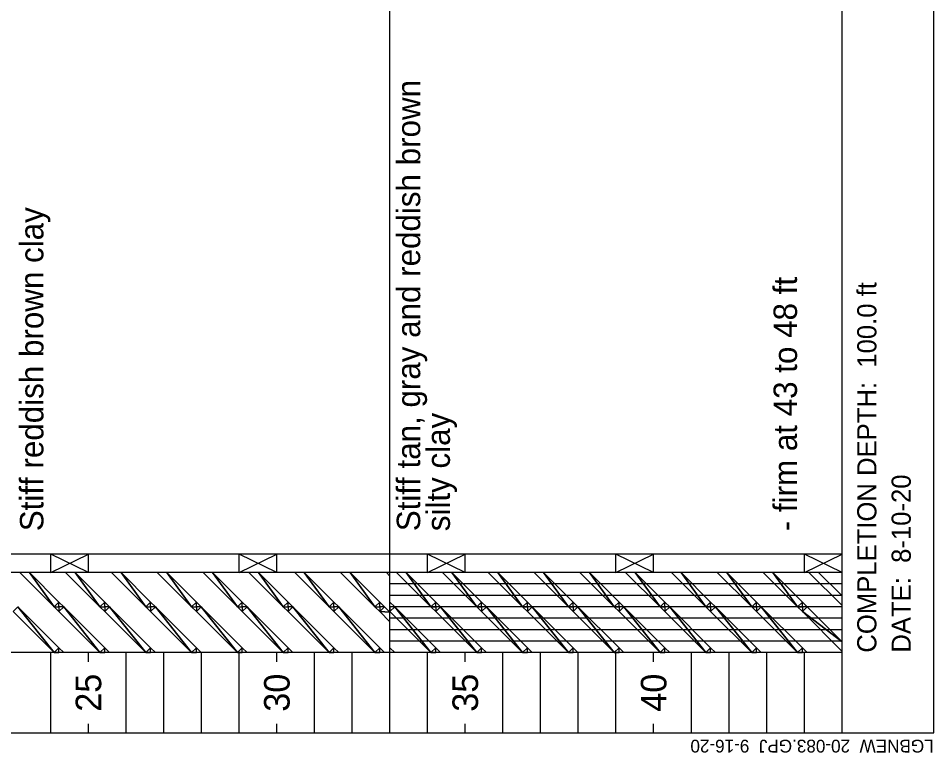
# Model space of a CAD drawing. Extents: x 1313964 to 1316843, y 2087046 to 2096619.
# Drawn here: x 1314012.51 to 1314036.8, y 2089818.18 to 2089837.67 of the extents above; entities that cross this region are included whole.
import ezdxf

# ---------------------------------------------------------------- set-up
doc = ezdxf.new("R2010")
doc.units = 0
doc.layers.add('B-Sub-Contour', color=7, linetype='Continuous')

msp = doc.modelspace()

# ---------------------------------------------------------------- linework, layer by layer
at = {"layer": 'B-Sub-Contour'}
for points in [[(1314036.804, 2089818.705), (1314036.804, 2089861.576), (1313975.385, 2089861.576), (1313975.385, 2089818.705), (1314036.804, 2089818.705)], [(1314034.372, 2089818.705), (1314034.372, 2089861.576)], [(1314022.372, 2089823.448), (1314022.372, 2089839.319)], [(1314034.372, 2089823.448), (1313989.372, 2089823.448)], [(1314013.372, 2089822.961), (1314014.372, 2089823.448)], [(1314014.372, 2089822.961), (1314013.372, 2089823.448)], [(1314013.372, 2089822.961), (1314013.372, 2089823.448)], [(1314014.372, 2089822.961), (1314014.372, 2089823.448)], [(1314018.372, 2089822.961), (1314019.372, 2089823.448)], [(1314019.372, 2089822.961), (1314018.372, 2089823.448)], [(1314018.372, 2089822.961), (1314018.372, 2089823.448)], [(1314019.372, 2089822.961), (1314019.372, 2089823.448)], [(1314022.372, 2089822.961), (1314022.372, 2089823.448)], [(1314023.372, 2089822.961), (1314024.372, 2089823.448)], [(1314024.372, 2089822.961), (1314023.372, 2089823.448)], [(1314023.372, 2089822.961), (1314023.372, 2089823.448)], [(1314024.372, 2089822.961), (1314024.372, 2089823.448)], [(1314028.372, 2089822.961), (1314029.372, 2089823.448)], [(1314029.372, 2089822.961), (1314028.372, 2089823.448)], [(1314028.372, 2089822.961), (1314028.372, 2089823.448)], [(1314029.372, 2089822.961), (1314029.372, 2089823.448)], [(1314033.372, 2089822.961), (1314034.372, 2089823.448)], [(1314034.372, 2089822.961), (1314033.372, 2089823.448)], [(1314033.372, 2089822.961), (1314033.372, 2089823.448)], [(1314034.372, 2089822.961), (1314034.372, 2089823.448)], [(1314034.372, 2089822.961), (1313982.683, 2089822.961)], [(1314022.372, 2089820.833), (1314022.372, 2089822.961)], [(1314034.372, 2089822.657), (1314022.372, 2089822.657)], [(1314034.372, 2089822.353), (1314022.372, 2089822.353)], [(1314034.372, 2089822.049), (1314022.372, 2089822.049)], [(1314034.372, 2089821.745), (1314022.372, 2089821.745)], [(1314034.372, 2089821.441), (1314022.372, 2089821.441)], [(1314034.372, 2089821.137), (1314022.372, 2089821.137)], [(1314034.372, 2089820.833), (1313982.683, 2089820.833)], [(1314013.372, 2089818.705), (1314013.372, 2089820.833)], [(1314013.372, 2089818.705), (1314013.372, 2089820.833)], [(1314014.372, 2089820.59), (1314014.372, 2089820.833)], [(1314015.372, 2089818.705), (1314015.372, 2089820.833)], [(1314015.372, 2089818.705), (1314015.372, 2089820.833)], [(1314016.372, 2089818.705), (1314016.372, 2089820.833)], [(1314017.372, 2089818.705), (1314017.372, 2089820.833)], [(1314017.372, 2089818.705), (1314017.372, 2089820.833)], [(1314018.372, 2089818.705), (1314018.372, 2089820.833)], [(1314019.372, 2089820.59), (1314019.372, 2089820.833)], [(1314019.372, 2089820.59), (1314019.372, 2089820.833)], [(1314020.372, 2089818.705), (1314020.372, 2089820.833)], [(1314021.372, 2089818.705), (1314021.372, 2089820.833)], [(1314021.372, 2089818.705), (1314021.372, 2089820.833)], [(1314022.372, 2089818.705), (1314022.372, 2089820.833)], [(1314023.372, 2089818.705), (1314023.372, 2089820.833)], [(1314023.372, 2089818.705), (1314023.372, 2089820.833)], [(1314024.372, 2089820.59), (1314024.372, 2089820.833)], [(1314025.372, 2089818.705), (1314025.372, 2089820.833)], [(1314025.372, 2089818.705), (1314025.372, 2089820.833)], [(1314026.372, 2089818.705), (1314026.372, 2089820.833)], [(1314027.372, 2089818.705), (1314027.372, 2089820.833)], [(1314027.372, 2089818.705), (1314027.372, 2089820.833)], [(1314028.372, 2089818.705), (1314028.372, 2089820.833)], [(1314029.372, 2089820.59), (1314029.372, 2089820.833)], [(1314029.372, 2089820.59), (1314029.372, 2089820.833)], [(1314030.372, 2089818.705), (1314030.372, 2089820.833)], [(1314031.372, 2089818.705), (1314031.372, 2089820.833)], [(1314031.372, 2089818.705), (1314031.372, 2089820.833)], [(1314032.372, 2089818.705), (1314032.372, 2089820.833)], [(1314033.372, 2089818.705), (1314033.372, 2089820.833)], [(1314033.372, 2089818.705), (1314033.372, 2089820.833)], [(1314034.372, 2089820.59), (1314034.372, 2089820.833)], [(1314014.372, 2089818.705), (1314014.372, 2089818.948)], [(1314019.372, 2089818.705), (1314019.372, 2089818.948)], [(1314019.372, 2089818.705), (1314019.372, 2089818.948)], [(1314024.372, 2089818.705), (1314024.372, 2089818.948)], [(1314029.372, 2089818.705), (1314029.372, 2089818.948)], [(1314029.372, 2089818.705), (1314029.372, 2089818.948)], [(1314034.372, 2089818.705), (1314034.372, 2089818.948)]]:
    msp.add_lwpolyline(points, dxfattribs=at)
for points in [[(1314013.46, 2089822.049), (1314012.803, 2089822.961), (1314012.547, 2089822.961), (1314013.46, 2089822.049)], [(1314013.46, 2089822.049), (1314013.588, 2089822.177), (1314012.803, 2089822.961), (1314013.46, 2089822.049)], [(1314014.676, 2089822.049), (1314014.02, 2089822.961), (1314013.764, 2089822.961), (1314014.676, 2089822.049)], [(1314014.676, 2089822.049), (1314014.804, 2089822.177), (1314014.02, 2089822.961), (1314014.676, 2089822.049)], [(1314015.893, 2089822.049), (1314015.236, 2089822.961), (1314014.98, 2089822.961), (1314015.893, 2089822.049)], [(1314015.893, 2089822.049), (1314016.02, 2089822.177), (1314015.236, 2089822.961), (1314015.893, 2089822.049)], [(1314017.109, 2089822.049), (1314016.452, 2089822.961), (1314016.197, 2089822.961), (1314017.109, 2089822.049)], [(1314017.109, 2089822.049), (1314017.237, 2089822.177), (1314016.452, 2089822.961), (1314017.109, 2089822.049)], [(1314018.325, 2089822.049), (1314017.668, 2089822.961), (1314017.413, 2089822.961), (1314018.325, 2089822.049)], [(1314018.325, 2089822.049), (1314018.453, 2089822.177), (1314017.668, 2089822.961), (1314018.325, 2089822.049)], [(1314019.541, 2089822.049), (1314018.884, 2089822.961), (1314018.629, 2089822.961), (1314019.541, 2089822.049)], [(1314019.541, 2089822.049), (1314019.669, 2089822.177), (1314018.884, 2089822.961), (1314019.541, 2089822.049)], [(1314020.757, 2089822.049), (1314020.101, 2089822.961), (1314019.845, 2089822.961), (1314020.757, 2089822.049)], [(1314020.757, 2089822.049), (1314020.885, 2089822.177), (1314020.101, 2089822.961), (1314020.757, 2089822.049)], [(1314021.974, 2089822.049), (1314021.317, 2089822.961), (1314021.062, 2089822.961), (1314021.974, 2089822.049)], [(1314021.974, 2089822.049), (1314022.101, 2089822.177), (1314021.317, 2089822.961), (1314021.974, 2089822.049)], [(1314022.372, 2089822.867), (1314022.372, 2089822.961), (1314022.278, 2089822.961), (1314022.372, 2089822.867)], [(1314023.46, 2089822.049), (1314022.803, 2089822.961), (1314022.547, 2089822.961), (1314023.46, 2089822.049)], [(1314023.46, 2089822.049), (1314023.588, 2089822.177), (1314022.803, 2089822.961), (1314023.46, 2089822.049)], [(1314024.676, 2089822.049), (1314024.02, 2089822.961), (1314023.764, 2089822.961), (1314024.676, 2089822.049)], [(1314024.676, 2089822.049), (1314024.804, 2089822.177), (1314024.02, 2089822.961), (1314024.676, 2089822.049)], [(1314025.893, 2089822.049), (1314025.236, 2089822.961), (1314024.98, 2089822.961), (1314025.893, 2089822.049)], [(1314025.893, 2089822.049), (1314026.02, 2089822.177), (1314025.236, 2089822.961), (1314025.893, 2089822.049)], [(1314027.109, 2089822.049), (1314026.452, 2089822.961), (1314026.197, 2089822.961), (1314027.109, 2089822.049)], [(1314027.109, 2089822.049), (1314027.236, 2089822.177), (1314026.452, 2089822.961), (1314027.109, 2089822.049)], [(1314028.325, 2089822.049), (1314027.668, 2089822.961), (1314027.413, 2089822.961), (1314028.325, 2089822.049)], [(1314028.325, 2089822.049), (1314028.453, 2089822.177), (1314027.668, 2089822.961), (1314028.325, 2089822.049)], [(1314029.541, 2089822.049), (1314028.884, 2089822.961), (1314028.629, 2089822.961), (1314029.541, 2089822.049)], [(1314029.541, 2089822.049), (1314029.669, 2089822.177), (1314028.884, 2089822.961), (1314029.541, 2089822.049)], [(1314030.757, 2089822.049), (1314030.101, 2089822.961), (1314029.845, 2089822.961), (1314030.757, 2089822.049)], [(1314030.757, 2089822.049), (1314030.885, 2089822.177), (1314030.101, 2089822.961), (1314030.757, 2089822.049)], [(1314031.974, 2089822.049), (1314031.317, 2089822.961), (1314031.061, 2089822.961), (1314031.974, 2089822.049)], [(1314031.974, 2089822.049), (1314032.101, 2089822.177), (1314031.317, 2089822.961), (1314031.974, 2089822.049)], [(1314033.19, 2089822.049), (1314032.533, 2089822.961), (1314032.278, 2089822.961), (1314033.19, 2089822.049)], [(1314033.19, 2089822.049), (1314033.318, 2089822.177), (1314032.533, 2089822.961), (1314033.19, 2089822.049)], [(1314033.749, 2089822.961), (1314033.494, 2089822.961), (1314034.372, 2089822.084), (1314034.372, 2089822.339)], [(1314013.46, 2089822.049), (1314013.588, 2089822.049), (1314013.588, 2089822.177), (1314013.46, 2089822.049)], [(1314013.716, 2089822.049), (1314013.588, 2089822.049), (1314013.588, 2089822.177), (1314013.716, 2089822.049)], [(1314014.676, 2089822.049), (1314014.804, 2089822.049), (1314014.804, 2089822.177), (1314014.676, 2089822.049)], [(1314014.932, 2089822.049), (1314014.804, 2089822.049), (1314014.804, 2089822.177), (1314014.932, 2089822.049)], [(1314015.893, 2089822.049), (1314016.02, 2089822.049), (1314016.02, 2089822.177), (1314015.893, 2089822.049)], [(1314016.148, 2089822.049), (1314016.02, 2089822.049), (1314016.02, 2089822.177), (1314016.148, 2089822.049)], [(1314017.109, 2089822.049), (1314017.237, 2089822.049), (1314017.237, 2089822.177), (1314017.109, 2089822.049)], [(1314017.364, 2089822.049), (1314017.237, 2089822.049), (1314017.237, 2089822.177), (1314017.364, 2089822.049)], [(1314018.325, 2089822.049), (1314018.453, 2089822.049), (1314018.453, 2089822.177), (1314018.325, 2089822.049)], [(1314018.58, 2089822.049), (1314018.453, 2089822.049), (1314018.453, 2089822.177), (1314018.58, 2089822.049)], [(1314019.541, 2089822.049), (1314019.669, 2089822.049), (1314019.669, 2089822.177), (1314019.541, 2089822.049)], [(1314019.797, 2089822.049), (1314019.669, 2089822.049), (1314019.669, 2089822.177), (1314019.797, 2089822.049)], [(1314020.757, 2089822.049), (1314020.885, 2089822.049), (1314020.885, 2089822.177), (1314020.757, 2089822.049)], [(1314021.013, 2089822.049), (1314020.885, 2089822.049), (1314020.885, 2089822.177), (1314021.013, 2089822.049)], [(1314021.974, 2089822.049), (1314022.101, 2089822.049), (1314022.101, 2089822.177), (1314021.974, 2089822.049)], [(1314022.229, 2089822.049), (1314022.101, 2089822.049), (1314022.101, 2089822.177), (1314022.229, 2089822.049)], [(1314022.499, 2089822.049), (1314022.372, 2089822.049), (1314022.372, 2089822.177), (1314022.499, 2089822.049)], [(1314023.46, 2089822.049), (1314023.588, 2089822.049), (1314023.588, 2089822.177), (1314023.46, 2089822.049)], [(1314023.716, 2089822.049), (1314023.588, 2089822.049), (1314023.588, 2089822.177), (1314023.716, 2089822.049)], [(1314024.676, 2089822.049), (1314024.804, 2089822.049), (1314024.804, 2089822.177), (1314024.676, 2089822.049)], [(1314024.932, 2089822.049), (1314024.804, 2089822.049), (1314024.804, 2089822.177), (1314024.932, 2089822.049)], [(1314025.893, 2089822.049), (1314026.02, 2089822.049), (1314026.02, 2089822.177), (1314025.893, 2089822.049)], [(1314026.148, 2089822.049), (1314026.02, 2089822.049), (1314026.02, 2089822.177), (1314026.148, 2089822.049)], [(1314027.109, 2089822.049), (1314027.236, 2089822.049), (1314027.236, 2089822.177), (1314027.109, 2089822.049)], [(1314027.364, 2089822.049), (1314027.236, 2089822.049), (1314027.236, 2089822.177), (1314027.364, 2089822.049)], [(1314028.325, 2089822.049), (1314028.453, 2089822.049), (1314028.453, 2089822.177), (1314028.325, 2089822.049)], [(1314028.58, 2089822.049), (1314028.453, 2089822.049), (1314028.453, 2089822.177), (1314028.58, 2089822.049)], [(1314029.541, 2089822.049), (1314029.669, 2089822.049), (1314029.669, 2089822.177), (1314029.541, 2089822.049)], [(1314029.797, 2089822.049), (1314029.669, 2089822.049), (1314029.669, 2089822.177), (1314029.797, 2089822.049)], [(1314030.757, 2089822.049), (1314030.885, 2089822.049), (1314030.885, 2089822.177), (1314030.757, 2089822.049)], [(1314031.013, 2089822.049), (1314030.885, 2089822.049), (1314030.885, 2089822.177), (1314031.013, 2089822.049)], [(1314031.974, 2089822.049), (1314032.101, 2089822.049), (1314032.101, 2089822.177), (1314031.974, 2089822.049)], [(1314032.229, 2089822.049), (1314032.101, 2089822.049), (1314032.101, 2089822.177), (1314032.229, 2089822.049)], [(1314033.19, 2089822.049), (1314033.318, 2089822.049), (1314033.318, 2089822.177), (1314033.19, 2089822.049)], [(1314033.445, 2089822.049), (1314033.318, 2089822.049), (1314033.318, 2089822.177), (1314033.445, 2089822.049)], [(1314013.46, 2089820.833), (1314012.499, 2089822.049), (1314012.372, 2089821.922), (1314013.46, 2089820.833)], [(1314013.46, 2089820.833), (1314013.588, 2089820.961), (1314012.499, 2089822.049), (1314013.46, 2089820.833)], [(1314013.588, 2089822.049), (1314013.588, 2089821.922), (1314013.46, 2089822.049), (1314013.588, 2089822.049)], [(1314013.716, 2089822.049), (1314013.588, 2089822.049), (1314013.588, 2089821.922), (1314013.716, 2089822.049)], [(1314014.676, 2089820.833), (1314013.716, 2089822.049), (1314013.588, 2089821.922), (1314014.676, 2089820.833)], [(1314014.676, 2089820.833), (1314014.804, 2089820.961), (1314013.716, 2089822.049), (1314014.676, 2089820.833)], [(1314014.804, 2089822.049), (1314014.804, 2089821.922), (1314014.676, 2089822.049), (1314014.804, 2089822.049)], [(1314014.932, 2089822.049), (1314014.804, 2089822.049), (1314014.804, 2089821.922), (1314014.932, 2089822.049)], [(1314015.893, 2089820.833), (1314014.932, 2089822.049), (1314014.804, 2089821.922), (1314015.893, 2089820.833)], [(1314015.893, 2089820.833), (1314016.02, 2089820.961), (1314014.932, 2089822.049), (1314015.893, 2089820.833)], [(1314016.02, 2089822.049), (1314016.02, 2089821.922), (1314015.893, 2089822.049), (1314016.02, 2089822.049)], [(1314016.148, 2089822.049), (1314016.02, 2089822.049), (1314016.02, 2089821.922), (1314016.148, 2089822.049)], [(1314017.109, 2089820.833), (1314016.148, 2089822.049), (1314016.02, 2089821.922), (1314017.109, 2089820.833)], [(1314017.109, 2089820.833), (1314017.237, 2089820.961), (1314016.148, 2089822.049), (1314017.109, 2089820.833)], [(1314017.237, 2089822.049), (1314017.237, 2089821.922), (1314017.109, 2089822.049), (1314017.237, 2089822.049)], [(1314017.364, 2089822.049), (1314017.237, 2089822.049), (1314017.237, 2089821.922), (1314017.364, 2089822.049)], [(1314018.325, 2089820.833), (1314017.364, 2089822.049), (1314017.237, 2089821.922), (1314018.325, 2089820.833)], [(1314018.325, 2089820.833), (1314018.453, 2089820.961), (1314017.364, 2089822.049), (1314018.325, 2089820.833)], [(1314018.453, 2089822.049), (1314018.453, 2089821.922), (1314018.325, 2089822.049), (1314018.453, 2089822.049)], [(1314018.58, 2089822.049), (1314018.453, 2089822.049), (1314018.453, 2089821.922), (1314018.58, 2089822.049)], [(1314019.541, 2089820.833), (1314018.58, 2089822.049), (1314018.453, 2089821.922), (1314019.541, 2089820.833)], [(1314019.541, 2089820.833), (1314019.669, 2089820.961), (1314018.58, 2089822.049), (1314019.541, 2089820.833)], [(1314019.669, 2089822.049), (1314019.669, 2089821.922), (1314019.541, 2089822.049), (1314019.669, 2089822.049)], [(1314019.797, 2089822.049), (1314019.669, 2089822.049), (1314019.669, 2089821.922), (1314019.797, 2089822.049)], [(1314020.757, 2089820.833), (1314019.797, 2089822.049), (1314019.669, 2089821.922), (1314020.757, 2089820.833)], [(1314020.757, 2089820.833), (1314020.885, 2089820.961), (1314019.797, 2089822.049), (1314020.757, 2089820.833)], [(1314020.885, 2089822.049), (1314020.885, 2089821.922), (1314020.757, 2089822.049), (1314020.885, 2089822.049)], [(1314021.013, 2089822.049), (1314020.885, 2089822.049), (1314020.885, 2089821.922), (1314021.013, 2089822.049)], [(1314021.974, 2089820.833), (1314021.013, 2089822.049), (1314020.885, 2089821.922), (1314021.974, 2089820.833)], [(1314021.974, 2089820.833), (1314022.101, 2089820.961), (1314021.013, 2089822.049), (1314021.974, 2089820.833)], [(1314022.101, 2089822.049), (1314022.101, 2089821.922), (1314021.974, 2089822.049), (1314022.101, 2089822.049)], [(1314022.229, 2089822.049), (1314022.101, 2089822.049), (1314022.101, 2089821.922), (1314022.229, 2089822.049)], [(1314022.101, 2089821.922), (1314022.372, 2089821.907), (1314022.229, 2089822.049), (1314022.101, 2089821.922)], [(1314022.499, 2089822.049), (1314022.372, 2089822.049), (1314022.372, 2089821.922), (1314022.499, 2089822.049)], [(1314023.46, 2089820.833), (1314022.499, 2089822.049), (1314022.372, 2089821.922), (1314023.46, 2089820.833)], [(1314023.46, 2089820.833), (1314023.588, 2089820.961), (1314022.499, 2089822.049), (1314023.46, 2089820.833)], [(1314023.588, 2089822.049), (1314023.588, 2089821.922), (1314023.46, 2089822.049), (1314023.588, 2089822.049)], [(1314023.716, 2089822.049), (1314023.588, 2089822.049), (1314023.588, 2089821.922), (1314023.716, 2089822.049)], [(1314024.676, 2089820.833), (1314023.716, 2089822.049), (1314023.588, 2089821.922), (1314024.676, 2089820.833)], [(1314024.676, 2089820.833), (1314024.804, 2089820.961), (1314023.716, 2089822.049), (1314024.676, 2089820.833)], [(1314024.804, 2089822.049), (1314024.804, 2089821.922), (1314024.676, 2089822.049), (1314024.804, 2089822.049)], [(1314024.932, 2089822.049), (1314024.804, 2089822.049), (1314024.804, 2089821.922), (1314024.932, 2089822.049)], [(1314025.893, 2089820.833), (1314024.932, 2089822.049), (1314024.804, 2089821.922), (1314025.893, 2089820.833)], [(1314025.893, 2089820.833), (1314026.02, 2089820.961), (1314024.932, 2089822.049), (1314025.893, 2089820.833)], [(1314026.02, 2089822.049), (1314026.02, 2089821.922), (1314025.893, 2089822.049), (1314026.02, 2089822.049)], [(1314026.148, 2089822.049), (1314026.02, 2089822.049), (1314026.02, 2089821.922), (1314026.148, 2089822.049)], [(1314027.109, 2089820.833), (1314026.148, 2089822.049), (1314026.02, 2089821.922), (1314027.109, 2089820.833)], [(1314027.109, 2089820.833), (1314027.236, 2089820.961), (1314026.148, 2089822.049), (1314027.109, 2089820.833)], [(1314027.236, 2089822.049), (1314027.236, 2089821.922), (1314027.109, 2089822.049), (1314027.236, 2089822.049)], [(1314027.364, 2089822.049), (1314027.236, 2089822.049), (1314027.236, 2089821.922), (1314027.364, 2089822.049)], [(1314028.325, 2089820.833), (1314027.364, 2089822.049), (1314027.236, 2089821.922), (1314028.325, 2089820.833)], [(1314028.325, 2089820.833), (1314028.453, 2089820.961), (1314027.364, 2089822.049), (1314028.325, 2089820.833)], [(1314028.453, 2089822.049), (1314028.453, 2089821.922), (1314028.325, 2089822.049), (1314028.453, 2089822.049)], [(1314028.58, 2089822.049), (1314028.453, 2089822.049), (1314028.453, 2089821.922), (1314028.58, 2089822.049)], [(1314029.541, 2089820.833), (1314028.58, 2089822.049), (1314028.453, 2089821.922), (1314029.541, 2089820.833)], [(1314029.541, 2089820.833), (1314029.669, 2089820.961), (1314028.58, 2089822.049), (1314029.541, 2089820.833)], [(1314029.669, 2089822.049), (1314029.669, 2089821.922), (1314029.541, 2089822.049), (1314029.669, 2089822.049)], [(1314029.797, 2089822.049), (1314029.669, 2089822.049), (1314029.669, 2089821.922), (1314029.797, 2089822.049)], [(1314030.757, 2089820.833), (1314029.797, 2089822.049), (1314029.669, 2089821.922), (1314030.757, 2089820.833)], [(1314030.757, 2089820.833), (1314030.885, 2089820.961), (1314029.797, 2089822.049), (1314030.757, 2089820.833)], [(1314030.885, 2089822.049), (1314030.885, 2089821.922), (1314030.757, 2089822.049), (1314030.885, 2089822.049)], [(1314031.013, 2089822.049), (1314030.885, 2089822.049), (1314030.885, 2089821.922), (1314031.013, 2089822.049)], [(1314031.974, 2089820.833), (1314031.013, 2089822.049), (1314030.885, 2089821.922), (1314031.974, 2089820.833)], [(1314031.974, 2089820.833), (1314032.101, 2089820.961), (1314031.013, 2089822.049), (1314031.974, 2089820.833)], [(1314032.101, 2089822.049), (1314032.101, 2089821.922), (1314031.974, 2089822.049), (1314032.101, 2089822.049)], [(1314032.229, 2089822.049), (1314032.101, 2089822.049), (1314032.101, 2089821.922), (1314032.229, 2089822.049)], [(1314033.19, 2089820.833), (1314032.229, 2089822.049), (1314032.101, 2089821.922), (1314033.19, 2089820.833)], [(1314033.19, 2089820.833), (1314033.318, 2089820.961), (1314032.229, 2089822.049), (1314033.19, 2089820.833)], [(1314033.318, 2089822.049), (1314033.318, 2089821.922), (1314033.19, 2089822.049), (1314033.318, 2089822.049)], [(1314033.445, 2089822.049), (1314033.318, 2089822.049), (1314033.318, 2089821.922), (1314033.445, 2089822.049)], [(1314033.318, 2089821.922), (1314034.372, 2089821.123), (1314033.445, 2089822.049), (1314033.318, 2089821.922)], [(1314022.101, 2089821.922), (1314022.372, 2089821.651), (1314022.372, 2089821.907), (1314022.101, 2089821.922)], [(1314033.318, 2089821.922), (1314034.372, 2089820.868), (1314034.372, 2089821.123), (1314033.318, 2089821.922)], [(1314013.46, 2089820.833), (1314013.588, 2089820.833), (1314013.588, 2089820.961), (1314013.46, 2089820.833)], [(1314013.716, 2089820.833), (1314013.588, 2089820.833), (1314013.588, 2089820.961), (1314013.716, 2089820.833)], [(1314014.676, 2089820.833), (1314014.804, 2089820.833), (1314014.804, 2089820.961), (1314014.676, 2089820.833)], [(1314014.932, 2089820.833), (1314014.804, 2089820.833), (1314014.804, 2089820.961), (1314014.932, 2089820.833)], [(1314015.893, 2089820.833), (1314016.02, 2089820.833), (1314016.02, 2089820.961), (1314015.893, 2089820.833)], [(1314016.148, 2089820.833), (1314016.02, 2089820.833), (1314016.02, 2089820.961), (1314016.148, 2089820.833)], [(1314017.109, 2089820.833), (1314017.237, 2089820.833), (1314017.237, 2089820.961), (1314017.109, 2089820.833)], [(1314017.364, 2089820.833), (1314017.237, 2089820.833), (1314017.237, 2089820.961), (1314017.364, 2089820.833)], [(1314018.325, 2089820.833), (1314018.453, 2089820.833), (1314018.453, 2089820.961), (1314018.325, 2089820.833)], [(1314018.58, 2089820.833), (1314018.453, 2089820.833), (1314018.453, 2089820.961), (1314018.58, 2089820.833)], [(1314019.541, 2089820.833), (1314019.669, 2089820.833), (1314019.669, 2089820.961), (1314019.541, 2089820.833)], [(1314019.797, 2089820.833), (1314019.669, 2089820.833), (1314019.669, 2089820.961), (1314019.797, 2089820.833)], [(1314020.757, 2089820.833), (1314020.885, 2089820.833), (1314020.885, 2089820.961), (1314020.757, 2089820.833)], [(1314021.013, 2089820.833), (1314020.885, 2089820.833), (1314020.885, 2089820.961), (1314021.013, 2089820.833)], [(1314021.974, 2089820.833), (1314022.101, 2089820.833), (1314022.101, 2089820.961), (1314021.974, 2089820.833)], [(1314022.229, 2089820.833), (1314022.101, 2089820.833), (1314022.101, 2089820.961), (1314022.229, 2089820.833)], [(1314022.499, 2089820.833), (1314022.372, 2089820.833), (1314022.372, 2089820.961), (1314022.499, 2089820.833)], [(1314023.46, 2089820.833), (1314023.588, 2089820.833), (1314023.588, 2089820.961), (1314023.46, 2089820.833)], [(1314023.716, 2089820.833), (1314023.588, 2089820.833), (1314023.588, 2089820.961), (1314023.716, 2089820.833)], [(1314024.676, 2089820.833), (1314024.804, 2089820.833), (1314024.804, 2089820.961), (1314024.676, 2089820.833)], [(1314024.932, 2089820.833), (1314024.804, 2089820.833), (1314024.804, 2089820.961), (1314024.932, 2089820.833)], [(1314025.893, 2089820.833), (1314026.02, 2089820.833), (1314026.02, 2089820.961), (1314025.893, 2089820.833)], [(1314026.148, 2089820.833), (1314026.02, 2089820.833), (1314026.02, 2089820.961), (1314026.148, 2089820.833)], [(1314027.109, 2089820.833), (1314027.236, 2089820.833), (1314027.236, 2089820.961), (1314027.109, 2089820.833)], [(1314027.364, 2089820.833), (1314027.236, 2089820.833), (1314027.236, 2089820.961), (1314027.364, 2089820.833)], [(1314028.325, 2089820.833), (1314028.453, 2089820.833), (1314028.453, 2089820.961), (1314028.325, 2089820.833)], [(1314028.58, 2089820.833), (1314028.453, 2089820.833), (1314028.453, 2089820.961), (1314028.58, 2089820.833)], [(1314029.541, 2089820.833), (1314029.669, 2089820.833), (1314029.669, 2089820.961), (1314029.541, 2089820.833)], [(1314029.797, 2089820.833), (1314029.669, 2089820.833), (1314029.669, 2089820.961), (1314029.797, 2089820.833)], [(1314030.757, 2089820.833), (1314030.885, 2089820.833), (1314030.885, 2089820.961), (1314030.757, 2089820.833)], [(1314031.013, 2089820.833), (1314030.885, 2089820.833), (1314030.885, 2089820.961), (1314031.013, 2089820.833)], [(1314031.974, 2089820.833), (1314032.101, 2089820.833), (1314032.101, 2089820.961), (1314031.974, 2089820.833)], [(1314032.229, 2089820.833), (1314032.101, 2089820.833), (1314032.101, 2089820.961), (1314032.229, 2089820.833)], [(1314033.19, 2089820.833), (1314033.318, 2089820.833), (1314033.318, 2089820.961), (1314033.19, 2089820.833)], [(1314033.445, 2089820.833), (1314033.318, 2089820.833), (1314033.318, 2089820.961), (1314033.445, 2089820.833)]]:
    msp.add_lwpolyline(points, close=True, dxfattribs=at)

# ---------------------------------------------------------------- texts
for s, height, rotation, p in [('Stiff tan, gray and reddish brown', 0.62209, 90, (1314023.176, 2089824.056)), ('Stiff reddish brown clay', 0.62209, 90, (1314013.176, 2089824.056)), ('- firm at 43 to 48 ft', 0.62209, 90, (1314033.176, 2089824.056)), ('COMPLETION DEPTH:  100.0 ft', 0.50899, 90, (1314035.284, 2089820.833)), ('silty clay', 0.6221, 90, (1314023.965, 2089824.056)), ('DATE:  8-10-20', 0.50899, 90, (1314036.196, 2089820.833)), ('25', 0.6786, 90, (1314014.711, 2089819.265)), ('30', 0.6786, 90, (1314019.711, 2089819.265)), ('30', 0.6786, 90, (1314019.711, 2089819.265)), ('35', 0.6786, 90, (1314024.711, 2089819.265)), ('40', 0.6786, 90, (1314029.711, 2089819.265)), ('40', 0.6786, 90, (1314029.711, 2089819.265)), ('LGBNEW  20-083.GPJ  9-16-20', 0.33932, 180, (1314036.804, 2089818.522))]:
    msp.add_text(s, height=height, rotation=rotation, dxfattribs=at).set_placement(p)

doc.saveas('drawing.dxf')
